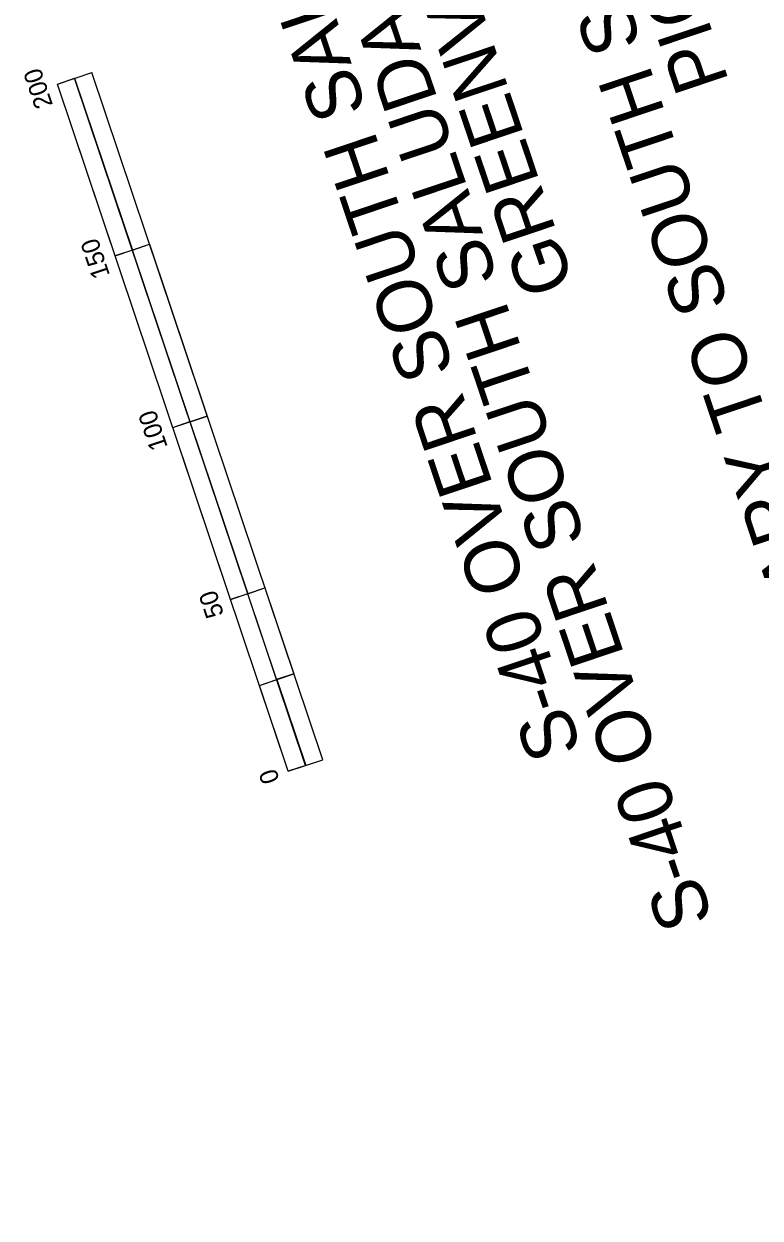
# Model space of a CAD drawing. Extents: x 1528853 to 1624411, y 1119753 to 1162242.
# Drawn here: x 1529749.9 to 1529952.8, y 1160751.2 to 1161080.6 of the extents above; entities that cross this region are included whole.
import ezdxf

# ---------------------------------------------------------------- set-up
doc = ezdxf.new("R2010")
doc.units = 0
doc.layers.add('RD_SHT_TX', color=7, linetype='Continuous')

msp = doc.modelspace()

# ---------------------------------------------------------------- linework, layer by layer
at = {"layer": 'RD_SHT_TX'}
for p, q in [((1529759.12, 1161064.02), (1529768.6, 1161067.2)), ((1529765.76, 1161066.24), (1529765.76, 1161066.24)), ((1529766.71, 1161066.56), (1529766.71, 1161066.56)), ((1529767.65, 1161066.88), (1529767.65, 1161066.88)), ((1529832.22, 1160877.65), (1529768.6, 1161067.2)), ((1529822.74, 1160874.47), (1529759.12, 1161064.02)), ((1529811.58, 1160923.44), (1529763.86, 1161065.61)), ((1529764.81, 1161065.93), (1529764.81, 1161065.93)), ((1529775.03, 1161016.62), (1529784.51, 1161019.81)), ((1529784.51, 1161019.81), (1529784.51, 1161019.81)), ((1529790.93, 1160969.24), (1529800.41, 1160972.42)), ((1529806.84, 1160921.85), (1529816.32, 1160925.03)), ((1529816.32, 1160925.03), (1529816.32, 1160925.03)), ((1529827.48, 1160876.06), (1529811.58, 1160923.44)), ((1529814.79, 1160898.16), (1529824.27, 1160901.34)), ((1529822.74, 1160874.47), (1529832.22, 1160877.65))]:
    msp.add_line(p, q, dxfattribs=at)
for points in [[(1529775.03, 1161016.62), (1529759.12, 1161064.02), (1529763.86, 1161065.61), (1529779.77, 1161018.22)], [(1529795.67, 1160970.83), (1529779.77, 1161018.22), (1529784.51, 1161019.81), (1529800.41, 1160972.42)], [(1529806.84, 1160921.85), (1529790.91, 1160969.31), (1529795.65, 1160970.9), (1529811.58, 1160923.44)], [(1529819.53, 1160899.75), (1529811.58, 1160923.44), (1529816.32, 1160925.03), (1529824.27, 1160901.34)], [(1529822.74, 1160874.47), (1529814.79, 1160898.16), (1529819.62, 1160899.78), (1529827.57, 1160876.09)]]:
    msp.add_lwpolyline(points, close=True, dxfattribs=at)

# ---------------------------------------------------------------- texts
for s, height, rotation, p in [('PICKENS COUNTY', 15, 108.5527, (1529944.29, 1161064.69)), ('S-26 OVER TRIBUTARY TO SOUTH SALUDA RIVER', 15, 108.5527, (1530028.11, 1160753.91)), ('GREENVILLE COUNTY', 15, 108.5527, (1529901.67, 1161008.61)), ('S-40 OVER SOUTH SALUDA RIVER', 15, 108.5527, (1529903.73, 1160880.45)), ('S-40 OVER SOUTH SALUDA OVERFLOW', 15, 108.5527, (1529939.93, 1160833.6)), ('200', 5, 108.5519, (1529757.9, 1161058.23)), ('150', 5, 108.5487, (1529773.65, 1161011.29)), ('100', 5, 108.5501, (1529789.56, 1160963.91)), ('50', 5, 108.5527, (1529805.06, 1160917.71)), ('0', 5, 108.5493, (1529820.4, 1160872))]:
    msp.add_text(s, height=height, rotation=rotation, dxfattribs=at).set_placement(p)

doc.saveas('drawing.dxf')
